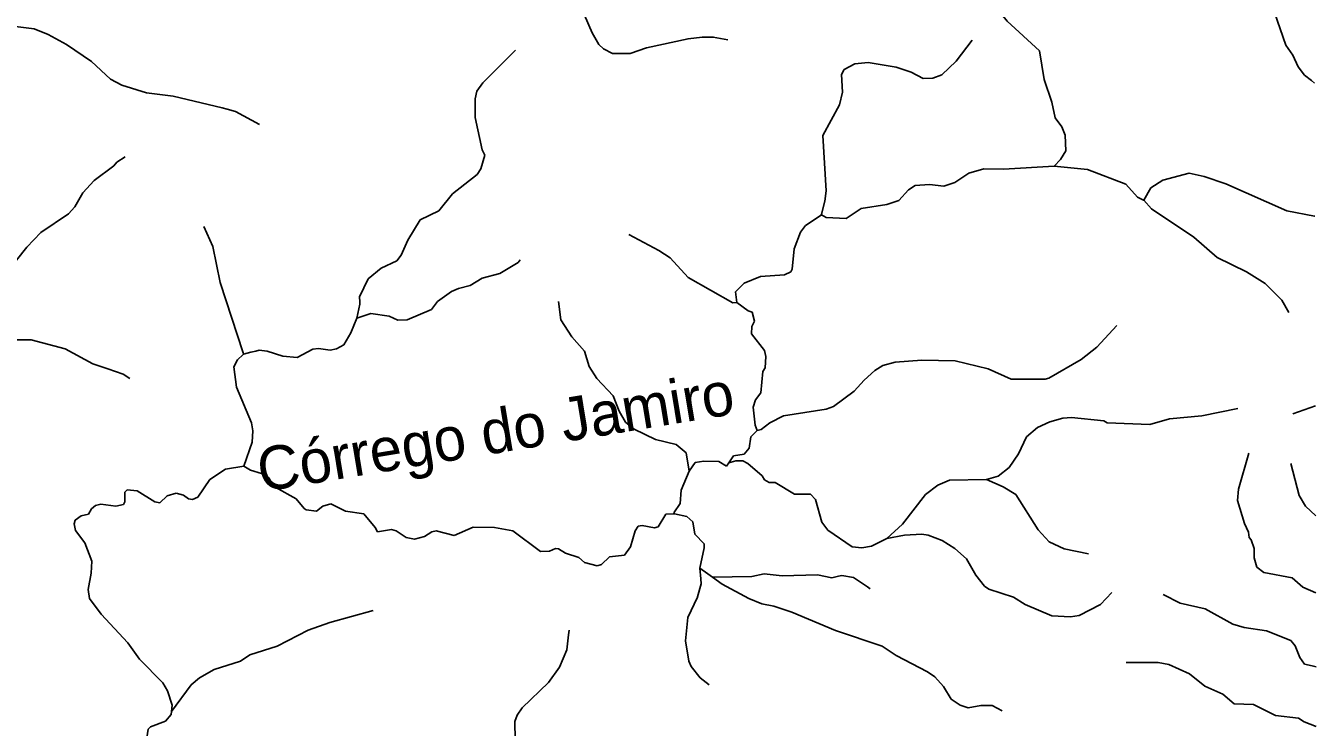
# Model space of a CAD drawing. Extents: x 393 to 446.6, y 8175.5 to 8231.
# Drawn here: x 440.67 to 446.6, y 8189.19 to 8192.41 of the extents above; entities that cross this region are included whole.
import ezdxf
from ezdxf.enums import TextEntityAlignment as Align

# ---------------------------------------------------------------- set-up
doc = ezdxf.new("R2010")
doc.units = 0
doc.header["$LTSCALE"] = 0.064
doc.linetypes.add('LONG_DASHED', pattern=[7.5, 6, -1.5])
doc.layers.add('61', color=7, linetype='Continuous')
doc.layers.add('7', color=7, linetype='Continuous', lineweight=25)
doc.layers.add('9', color=7, linetype='LONG_DASHED', lineweight=25)

msp = doc.modelspace()

# ---------------------------------------------------------------- linework, layer by layer
at = {"layer": '7'}
msp.add_line((446.4962, 8190.6283), (446.5995, 8190.6648), dxfattribs=at)
for points in [[(443.8977, 8192.3492), (443.8317, 8192.3618), (443.78, 8192.3618), (443.7154, 8192.3537), (443.5249, 8192.3117), (443.449, 8192.2859), (443.3682, 8192.2859), (443.3262, 8192.3069), (443.3052, 8192.3278), (443.2745, 8192.3812), (443.239, 8192.4619), (443.1954, 8192.52), (443.0791, 8192.7397), (443.0188, 8192.8098)], [(446.5958, 8192.1499), (446.5814, 8192.1612), (446.5488, 8192.1868), (446.5197, 8192.2252), (446.4961, 8192.2778), (446.4638, 8192.3246), (446.4121, 8192.4748), (446.3992, 8192.5297), (446.3959, 8192.6008), (446.4024, 8192.6331), (446.4492, 8192.7106), (446.4702, 8192.7623), (446.483, 8192.8048)], [(441.7462, 8191.9592), (441.6355, 8192.0194), (441.5968, 8192.0307), (441.5739, 8192.0362), (441.3481, 8192.0905), (441.3117, 8192.0948), (441.2254, 8192.105), (441.1124, 8192.1405), (441.0607, 8192.168), (440.9735, 8192.2488), (440.8588, 8192.3278), (440.7733, 8192.3731), (440.7103, 8192.3989), (440.6118, 8192.4118)], [(441.1275, 8191.8102), (441.0902, 8191.7869), (441.0752, 8191.7692), (440.9848, 8191.7013), (440.9331, 8191.6448), (440.8959, 8191.5802), (440.8669, 8191.5479), (440.7409, 8191.4623), (440.6763, 8191.3945), (440.5875, 8191.2831), (440.5149, 8191.2185), (440.4535, 8191.1926), (440.3793, 8191.1781), (440.3147, 8191.149), (440.264, 8191.1414)], [(440.264, 8191.1414), (440.3711, 8191.0796), (440.4325, 8191.0279), (440.4729, 8191.0037), (440.5504, 8190.9779), (440.615, 8190.9682), (440.6958, 8190.9682), (440.8524, 8190.9278), (440.98, 8190.8584), (441.048, 8190.8355), (441.1188, 8190.8116), (441.1493, 8190.7915)], [(446.4864, 8190.3995), (446.5254, 8190.2524), (446.5538, 8190.2038), (446.6007, 8190.1597)], [(445.8999, 8189.7974), (445.9781, 8189.7576), (446.0921, 8189.731), (446.2203, 8189.6606), (446.2725, 8189.6458), (446.3746, 8189.6299), (446.4862, 8189.5856), (446.5068, 8189.5608), (446.5283, 8189.5069), (446.55, 8189.4775), (446.5849, 8189.4691), (446.6024, 8189.4649)], [(445.7289, 8189.4852), (445.8759, 8189.4841), (445.9258, 8189.4755), (446.0206, 8189.4328), (446.0918, 8189.3763), (446.1735, 8189.3384), (446.2256, 8189.2942), (446.3142, 8189.2906), (446.4164, 8189.2411), (446.5218, 8189.2277), (446.5471, 8189.2115), (446.6031, 8189.19)]]:
    msp.add_lwpolyline(points, dxfattribs=at)
at = {"layer": '9'}
for points in [[(445.0324, 8192.5739), (445.0816, 8192.5598), (445.1825, 8192.4349), (445.3305, 8192.2992), (445.3523, 8192.1667), (445.3882, 8192.0628), (445.4025, 8191.9901), (445.4333, 8191.9483), (445.4496, 8191.9103), (445.4523, 8191.8381), (445.4281, 8191.7992), (445.3987, 8191.7671)], [(445.0218, 8192.3479), (444.9473, 8192.2506), (444.8822, 8192.1887), (444.8414, 8192.1723), (444.7956, 8192.1715), (444.7417, 8192.2004), (444.6726, 8192.2239), (444.544, 8192.244), (444.4829, 8192.239), (444.4333, 8192.2133), (444.4208, 8192.1892), (444.4256, 8192.1081), (444.4112, 8192.0501), (444.3357, 8191.9096), (444.3499, 8191.6551), (444.345, 8191.6076), (444.3291, 8191.5463), (444.3282, 8191.5429)], [(442.9221, 8192.3016), (442.7723, 8192.1517), (442.7446, 8192.1133), (442.7368, 8192.0782), (442.7374, 8191.9911), (442.7687, 8191.8437), (442.7815, 8191.8189), (442.7628, 8191.7551), (442.7458, 8191.7298), (442.6326, 8191.6408), (442.5693, 8191.5631), (442.4841, 8191.5211), (442.4281, 8191.4278), (442.3966, 8191.3585), (442.3764, 8191.3317), (442.3042, 8191.2992), (442.2455, 8191.2502), (442.2059, 8191.1675), (442.2067, 8191.1431), (442.207, 8191.1333), (442.193, 8191.0691)], [(444.3282, 8191.5429), (444.3294, 8191.5437), (444.351, 8191.5316), (444.4431, 8191.5264), (444.5117, 8191.5736), (444.6286, 8191.5914), (444.6851, 8191.6092), (444.7282, 8191.6596), (444.7602, 8191.6785), (444.826, 8191.6836), (444.8914, 8191.6757), (444.9414, 8191.6925), (445.0065, 8191.7363), (445.0757, 8191.7562), (445.1657, 8191.7547), (445.3987, 8191.7671)], [(445.3987, 8191.7671), (445.5514, 8191.7524), (445.7284, 8191.6852), (445.7814, 8191.6251), (445.8099, 8191.6112), (445.8102, 8191.6118)], [(445.8102, 8191.6118), (445.8436, 8191.6684), (445.8984, 8191.7033), (446.0184, 8191.7364), (446.0878, 8191.7209), (446.1879, 8191.6866), (446.4685, 8191.5618), (446.5946, 8191.5383), (446.5973, 8191.5378)], [(446.4766, 8191.0942), (446.4444, 8191.1521), (446.3685, 8191.2281), (446.2823, 8191.2816), (446.1474, 8191.3477), (446.0406, 8191.4411), (445.8465, 8191.5711), (445.8102, 8191.6118)], [(441.489, 8191.491), (441.5306, 8191.3987), (441.5643, 8191.232), (441.6697, 8190.9086), (441.6715, 8190.9031), (441.6717, 8190.9025)], [(443.9395, 8191.1403), (443.9343, 8191.1903), (443.9735, 8191.2292), (444.048, 8191.2602), (444.1583, 8191.2682), (444.1876, 8191.2814), (444.1946, 8191.2935), (444.2026, 8191.3881), (444.2324, 8191.4644), (444.2553, 8191.495), (444.3282, 8191.5429)], [(443.4433, 8191.4537), (443.5814, 8191.3799), (443.6328, 8191.3455), (443.7165, 8191.2561), (443.9208, 8191.1391), (443.9395, 8191.1403)], [(442.9445, 8191.3373), (442.9342, 8191.3251), (442.8499, 8191.2736), (442.7697, 8191.2524), (442.7143, 8191.2186), (442.6598, 8191.2056), (442.6276, 8191.1911), (442.5631, 8191.1446), (442.5354, 8191.1091), (442.4237, 8191.0603), (442.382, 8191.059), (442.3409, 8191.0777), (442.2565, 8191.0906), (442.193, 8191.0691)], [(443.1205, 8191.1454), (443.1306, 8191.0614), (443.1812, 8190.9823), (443.2388, 8190.9162), (443.2603, 8190.8465), (443.2957, 8190.7908), (443.3716, 8190.7107), (443.3994, 8190.6411), (443.428, 8190.5905), (443.4673, 8190.5576), (443.5661, 8190.51), (443.6605, 8190.4872), (443.7073, 8190.4492), (443.7204, 8190.364)], [(444.034, 8190.5514), (444.0235, 8190.5759), (444.0156, 8190.6589), (444.0259, 8190.6922), (444.0495, 8190.725), (444.0592, 8190.8235), (444.0706, 8190.8398), (444.0738, 8190.8922), (444.067, 8190.9199), (444.0078, 8190.9958), (444.0092, 8191.0305), (444.0217, 8191.0555), (444.0096, 8191.0968), (443.9922, 8191.1027), (443.9395, 8191.1403)], [(442.193, 8191.0691), (442.1651, 8191.0015), (442.1324, 8190.9452), (442.0994, 8190.927), (442.0703, 8190.9216), (442.0167, 8190.9292), (441.9901, 8190.9259), (441.9188, 8190.8877), (441.8527, 8190.8938), (441.7814, 8190.9161), (441.7434, 8190.9212), (441.729, 8190.9175), (441.7061, 8190.9115), (441.6717, 8190.9025)], [(445.6862, 8191.0347), (445.5948, 8190.9358), (445.5222, 8190.8778), (445.3748, 8190.7921), (445.357, 8190.7873), (445.2006, 8190.7874), (445.0951, 8190.8359), (444.9441, 8190.8729), (444.7896, 8190.8759), (444.6676, 8190.8658), (444.6109, 8190.8504), (444.5735, 8190.8285), (444.5244, 8190.7841), (444.4799, 8190.7321), (444.3837, 8190.6622), (444.3498, 8190.6497), (444.1546, 8190.6191), (444.0916, 8190.587), (444.0518, 8190.5559), (444.034, 8190.5514)], [(441.6717, 8190.9025), (441.6704, 8190.9022), (441.6449, 8190.8769), (441.6277, 8190.8445), (441.64, 8190.7517), (441.7084, 8190.5869), (441.7145, 8190.5499), (441.7124, 8190.4978), (441.6735, 8190.3885)], [(446.2429, 8190.6525), (446.077, 8190.6196), (445.9286, 8190.6048), (445.8378, 8190.579), (445.6429, 8190.5871), (445.6263, 8190.5967), (445.4787, 8190.6112), (445.4386, 8190.608), (445.3794, 8190.5921), (445.3225, 8190.5659), (445.2719, 8190.5222), (445.2339, 8190.4446), (445.1913, 8190.3822), (445.1405, 8190.3422), (445.0869, 8190.3269)], [(443.9029, 8190.4031), (443.9238, 8190.4348), (443.9731, 8190.4433), (443.9968, 8190.47), (444.0045, 8190.5228), (444.034, 8190.5514)], [(446.293, 8190.4473), (446.246, 8190.2825), (446.2411, 8190.2292), (446.2729, 8190.1243), (446.2912, 8190.0839), (446.2943, 8190.0595), (446.304, 8190.0486), (446.3176, 8190.0096), (446.3187, 8189.9663), (446.3306, 8189.9233), (446.3618, 8189.8989), (446.4934, 8189.8735), (446.542, 8189.8311), (446.6016, 8189.8043)], [(441.6735, 8190.3885), (441.5889, 8190.3745), (441.5167, 8190.3258), (441.4614, 8190.2454), (441.4379, 8190.2349), (441.4184, 8190.2377), (441.3959, 8190.2543), (441.362, 8190.2637), (441.3212, 8190.2511), (441.2873, 8190.2196), (441.264, 8190.2242), (441.1826, 8190.2738), (441.1371, 8190.2796), (441.1258, 8190.2677), (441.1268, 8190.2237), (441.1205, 8190.2121), (441.0856, 8190.2038), (441.0167, 8190.2128), (440.9917, 8190.2065), (440.9724, 8190.192), (440.959, 8190.167), (440.9252, 8190.1586), (440.8982, 8190.14), (440.8939, 8190.1227), (440.9002, 8190.0917), (440.9419, 8190.0358), (440.9747, 8189.9514), (440.9718, 8189.8953), (440.9574, 8189.8207), (440.9643, 8189.7789), (441.0176, 8189.7065), (441.1401, 8189.5756), (441.1931, 8189.5005), (441.3012, 8189.3904), (441.3228, 8189.3548), (441.3442, 8189.2876), (441.3406, 8189.2588)], [(441.6735, 8190.3885), (441.7038, 8190.3696), (441.7551, 8190.3541), (441.7879, 8190.3341), (441.8043, 8190.3055), (441.821, 8190.2902), (441.9142, 8190.2373), (441.9515, 8190.1933), (441.9599, 8190.1863), (442.0074, 8190.1803), (442.0359, 8190.2039), (442.073, 8190.2147), (442.1402, 8190.1804), (442.2245, 8190.168), (442.2774, 8190.1061), (442.2873, 8190.0859), (442.3522, 8190.0965), (442.3736, 8190.0897), (442.4197, 8190.0592), (442.4581, 8190.0526), (442.5047, 8190.0637), (442.5381, 8190.0855), (442.5581, 8190.0905), (442.641, 8190.0689), (442.7273, 8190.1073), (442.8251, 8190.105), (442.9103, 8190.0909), (443.0368, 8189.9957), (443.0783, 8189.9966), (443.1065, 8190.009), (443.1198, 8190.008), (443.1519, 8189.9882), (443.2128, 8189.967), (443.2401, 8189.9449), (443.2983, 8189.93), (443.3169, 8189.935), (443.3547, 8189.9702), (443.4226, 8189.9781), (443.4231, 8189.9787), (443.4508, 8190.0168), (443.4731, 8190.0899), (443.4868, 8190.1113), (443.5042, 8190.1142), (443.5611, 8190.1041), (443.5776, 8190.1083), (443.6137, 8190.1675), (443.6533, 8190.168)], [(443.6533, 8190.168), (443.6509, 8190.1731), (443.6797, 8190.2164), (443.6832, 8190.2771), (443.7204, 8190.364)], [(443.7204, 8190.364), (443.7477, 8190.4043), (443.7879, 8190.4107), (443.8577, 8190.4098), (443.8928, 8190.3878), (443.9029, 8190.4031)], [(444.6288, 8190.0552), (444.5581, 8190.0198), (444.5138, 8190.0115), (444.4707, 8190.0174), (444.3575, 8190.0934), (444.3304, 8190.1308), (444.3016, 8190.2342), (444.2782, 8190.2582), (444.205, 8190.2594), (444.1158, 8190.3123), (444.113, 8190.3123), (444.089, 8190.3127), (444.0671, 8190.3245), (444.0559, 8190.3432), (443.9905, 8190.4006), (443.9671, 8190.4124), (443.9356, 8190.4127), (443.9029, 8190.4031)], [(445.0869, 8190.3269), (444.9174, 8190.3238), (444.8633, 8190.301), (444.8066, 8190.2572), (444.7016, 8190.1207), (444.6288, 8190.0552)], [(445.5564, 8189.9848), (445.4445, 8190.0076), (445.3749, 8190.0402), (445.3249, 8190.0953), (445.223, 8190.2577), (445.1646, 8190.2927), (445.0869, 8190.3269)], [(443.7696, 8189.9184), (443.7903, 8190.012), (443.7897, 8190.0307), (443.7467, 8190.0746), (443.7376, 8190.1315), (443.7093, 8190.1565), (443.6533, 8190.168)], [(445.6636, 8189.8064), (445.6116, 8189.7515), (445.5133, 8189.7008), (445.473, 8189.6942), (445.3882, 8189.699), (445.2656, 8189.7507), (445.2122, 8189.7844), (445.0987, 8189.8213), (445.0781, 8189.8364), (445.0378, 8189.8865), (444.996, 8189.962), (444.9419, 8190.0094), (444.883, 8190.0451), (444.8199, 8190.0701), (444.7897, 8190.075), (444.7109, 8190.07), (444.6288, 8190.0552)], [(443.8132, 8189.3817), (443.7714, 8189.4136), (443.7292, 8189.466), (443.7185, 8189.4913), (443.7041, 8189.5843), (443.7151, 8189.6914), (443.7585, 8189.7855), (443.7591, 8189.7867), (443.7764, 8189.847), (443.7742, 8189.8697), (443.7696, 8189.9184)], [(443.8283, 8189.8766), (443.8059, 8189.8925), (443.7696, 8189.9184)], [(444.553, 8189.8231), (444.5398, 8189.8322), (444.4757, 8189.8763), (444.4222, 8189.8846), (444.4075, 8189.881), (444.3762, 8189.8735), (444.3109, 8189.8879), (444.1475, 8189.883), (444.0659, 8189.8925), (444.0086, 8189.8798), (443.8283, 8189.8766)], [(445.1594, 8189.2627), (445.114, 8189.2871), (445.061, 8189.2871), (445.0033, 8189.2761), (444.9665, 8189.2882), (444.9249, 8189.3165), (444.8893, 8189.3734), (444.8505, 8189.4179), (444.8165, 8189.4414), (444.6728, 8189.5166), (444.6085, 8189.5595), (444.3929, 8189.6314), (444.1927, 8189.7168), (444.1094, 8189.744), (444.0545, 8189.754), (443.9945, 8189.7783), (443.8729, 8189.8448), (443.8283, 8189.8766)], [(442.2683, 8189.724), (442.0688, 8189.6684), (441.9696, 8189.6326), (441.8265, 8189.5604), (441.7003, 8189.5195), (441.6588, 8189.4904), (441.5369, 8189.4524), (441.4697, 8189.4139), (441.4317, 8189.3822), (441.3406, 8189.2588)], [(443.1687, 8189.6329), (443.1662, 8189.6112), (443.1581, 8189.5423), (443.1242, 8189.463), (443.0741, 8189.3923), (442.9527, 8189.2754), (442.9293, 8189.2425), (442.9193, 8189.2135), (442.9193, 8189.2127), (442.9207, 8189.1291), (442.9003, 8189.0335)], [(441.3406, 8189.2588), (441.3389, 8189.2456), (441.3138, 8189.2141), (441.2445, 8189.1884), (441.233, 8189.1774), (441.228, 8189.1378), (441.2142, 8189.1117), (441.2011, 8189.1091), (441.156, 8189.1251), (441.1281, 8189.1182), (441.1178, 8189.048), (441.1052, 8189.0292), (441.0836, 8189.0201), (440.9799, 8189.0432), (440.938, 8189.0431), (440.9217, 8189.0356), (440.9011, 8189.004), (440.8981, 8188.8733), (440.8746, 8188.8458), (440.851, 8188.8384), (440.7924, 8188.8375), (440.7271, 8188.8593), (440.7119, 8188.8644)]]:
    msp.add_lwpolyline(points, dxfattribs=at)

# ---------------------------------------------------------------- texts
at = {"layer": '61'}
msp.add_text('Córrego do Jamiro', height=0.2, rotation=9.374, dxfattribs=at).set_placement((442.8461, 8190.4491), align=Align.CENTER)

doc.saveas('drawing.dxf')
